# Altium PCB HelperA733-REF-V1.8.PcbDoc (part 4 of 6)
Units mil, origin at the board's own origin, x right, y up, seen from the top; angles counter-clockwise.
Board outline 5905.51 x 4133.86 mil, 2 copper layers (Top, Bottom), stack 12.7 mil thick; 475 components, 355 nets, 1867 pads, 1471 vias.
Unrouted connection lines stored in the file: 1178.
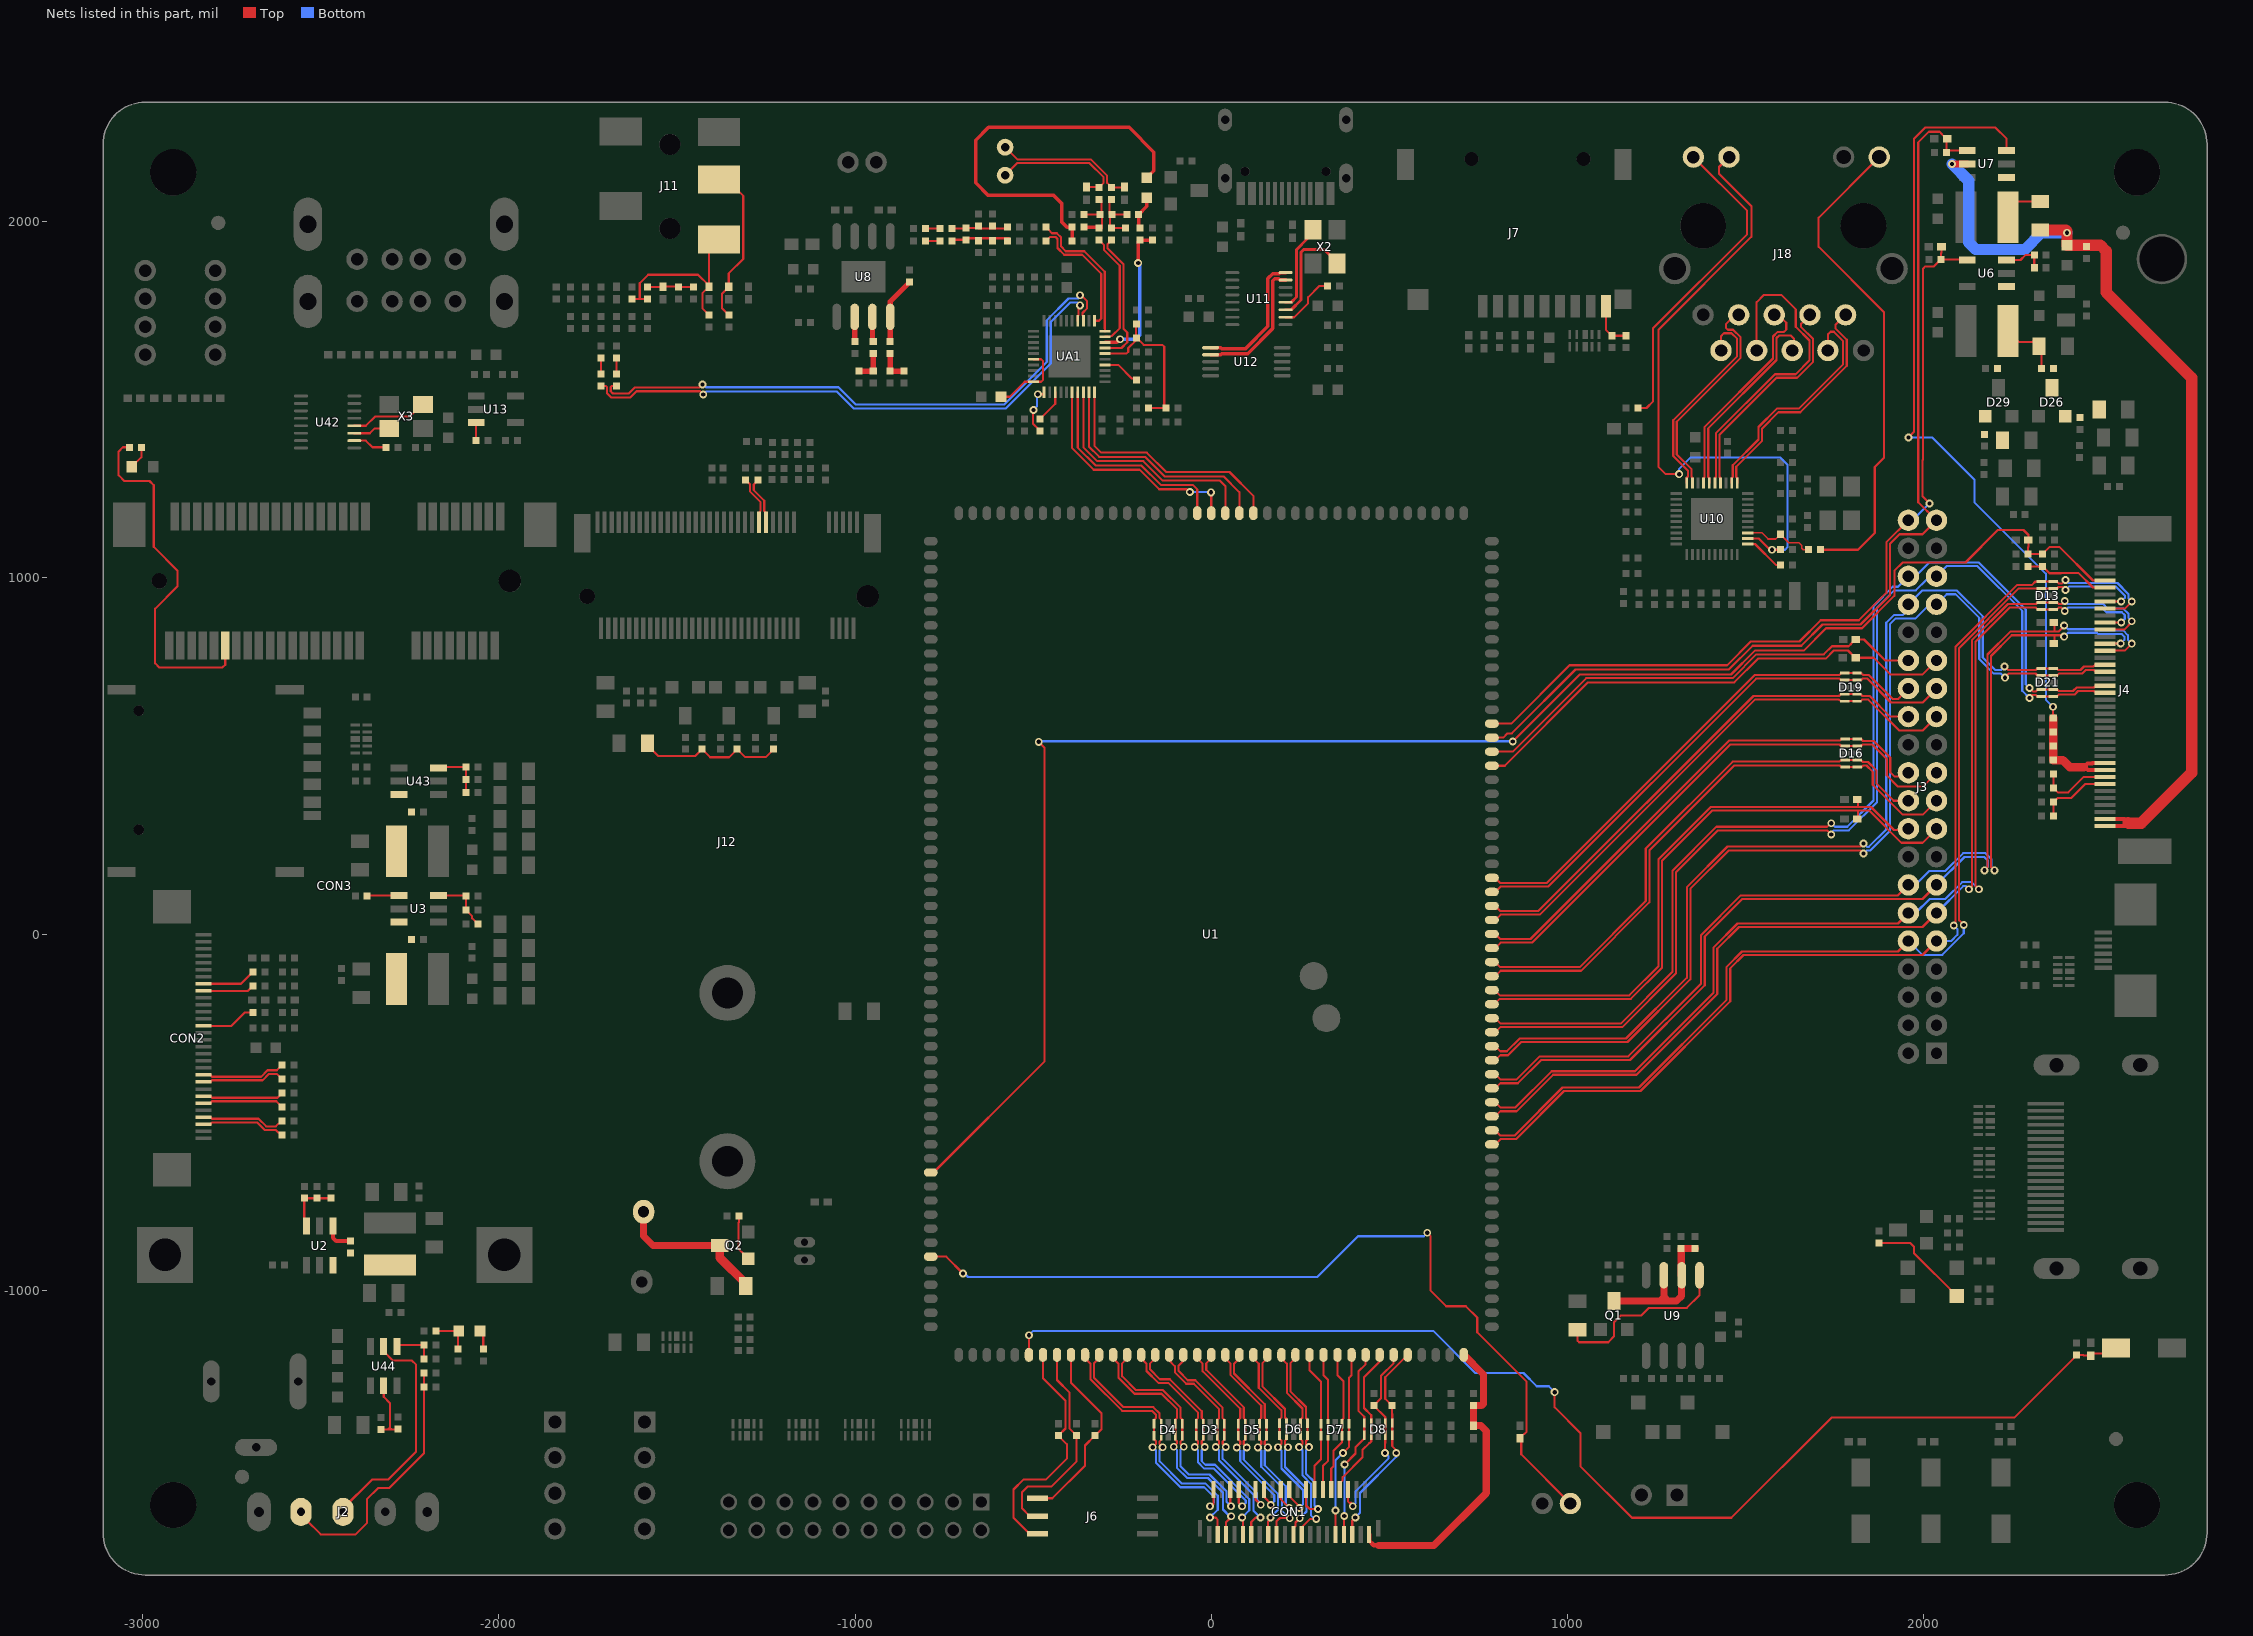
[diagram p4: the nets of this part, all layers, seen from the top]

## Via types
v1: diameter 22, hole 12, Top to Bottom, 1469 vias
v2: diameter 39.37, hole 35.43, Top to Bottom, 2 vias

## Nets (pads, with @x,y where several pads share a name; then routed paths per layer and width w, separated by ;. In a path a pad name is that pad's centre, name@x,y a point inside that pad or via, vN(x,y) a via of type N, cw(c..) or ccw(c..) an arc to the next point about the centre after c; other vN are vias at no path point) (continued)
HUB1-DM3: U11.15 U12.2 | length 378.6
  Top w10: U12.2@-1.97,1625.98 26.65,1625.98 29.5,1628.83 101.91,1628.83 172.8,1699.72 172.8,1833.45 178.42,1839.06 189.74,1839.06 193.17,1835.63 U11.15@208.66,1835.63
HUB1-DP3: U11.16 U12.1 | length 378.9
  Top w10: U12.1@-1.97,1645.67 26.65,1645.67 29.5,1642.83 96.11,1642.83 158.78,1705.49 158.78,1839.68 172.16,1853.06 190.16,1853.06 193.59,1856.5 U11.16@208.66,1856.5
I2S0-BCLK: U1.111 UA1.29 | length 686.7
  Top w6: UA1.29@-343.31,1520.69 -343.31,1368.08 -314.43,1339.2 -186.15,1339.2 -131.51,1284.57 34.33,1284.57 78.74,1240.16 U1.111@78.74,1181.1
I2S0-DIN0: U1.114 UA1.27 | length 606.3
  Top w6: UA1.27@-374.81,1520.69 -374.81,1365.29 -324.72,1315.2 -196.14,1315.2 -141.47,1260.53 -52,1260.53 -39.37,1247.91 U1.114@-39.37,1181.1
I2S0-DOUT0: U1.113 UA1.26 | length 658
  Top w6: UA1.26@-390.56,1520.69 -390.56,1363.83 -329.93,1303.2 -201.11,1303.2 -146.43,1248.52 -68.31,1248.52 v1(-60.24,1240.46) ; v1(-0.82,1239.57) 0,1238.75 U1.113@0,1181.1
  Bottom w6: v1(-60.24,1240.46) -0.34,1240.46 v1(-0.82,1239.57)
I2S0-LRCK: U1.112 UA1.28 | length 674.1
  Top w6: UA1.28@-359.06,1520.69 -359.06,1366.62 -319.64,1327.2 -191.12,1327.2 -136.46,1272.54 24.32,1272.54 39.37,1257.49 U1.112@39.37,1181.1
I2S0-MCLK: U1.110 UA1.30 | length 703.4
  Top w6: UA1.30@-327.56,1520.69 -327.56,1369.53 -309.24,1351.2 -181.17,1351.2 -126.61,1296.64 51.18,1296.64 118.11,1229.71 U1.110@118.11,1181.1
INTB: RE1.2 U10.31 | length 116
  Top w6: U10.31@1505.91,1094.49 1526.19,1094.49 1585.24,1035.43 RE1.2@1597.44,1035.43
IO-RESET: D42.1 K4.1 R54.2 U1.6 | length 3615.7
  Top w6: U1.6@-511.81,-1173.23 U1.6@-511.81,-1181.1 v1(-511.81,-1125.98) ; v1(963.74,-1285.8) 963.74,-1328.12 1036.06,-1400.44 1036.06,-1493.61 1180.9,-1638.46 1459.77,-1638.46 1740.91,-1357.32 2253.9,-1357.32 R54.2@2429.13,-1182.09 2448.11,-1182.09 2449.37,-1183.35 D42.1@2468.5,-1183.35 2468.5,-1181.35 2472.69,-1177.17 2523.62,-1177.17 K4.1@2539.37,-1161.42
  Bottom w6: v1(-511.81,-1125.98) -499.68,-1113.86 622.54,-1113.86 741.03,-1232.34 876.08,-1232.34 913.15,-1269.42 947.35,-1269.42 v1(963.74,-1285.8)
IOVDD-CSI: CON1.39 CP4.1 D12.2 U1.37 | length 874.9
  Top w12: CON1.39@443.04,-1685 443.04,-1702.72 456.18,-1715.86 469.55,-1715.86
  Top w20: 469.55,-1715.86 625.47,-1715.86 771.89,-1569.45 771.89,-1395.3 756.22,-1379.64 D12.2@736.22,-1379.64 CP4.1@736.22,-1323.82 758.78,-1323.82 763.78,-1318.82 763.78,-1236.22 U1.37@708.66,-1181.1
LCD0-EN: D22.1 J3.40 R41.2 U1.81 U6.4 | length 2426.8
  Top w6: U1.81@787.4,590.55 841.66,590.55 1005.44,754.33 1447.71,754.33 1514.54,821.16 1651.14,821.16 1710.62,880.64 1817.44,880.64 1894.67,957.86 1894.67,1099.4 J3.40@1956.69,1161.42 ; v1(2015.75,1208.66) 1996.06,1228.35 1996.06,1329.17 1997.6,1330.71 1997.6,1867.68 2003.94,1874.02 2028.54,1874.02 R41.2@2048.23,1893.7 ; D22.1@2049.5,1929.13 2049.5,1911.97 2048.23,1910.7 R41.2@2048.23,1893.7 ; U6.4@2122.05,1891.73 2131.89,1891.73 2129.92,1893.7 R41.2@2048.23,1893.7
  Bottom w6: J3.40@1956.69,1161.42 1964.57,1169.29 1976.38,1169.29 v1(2015.75,1208.66)
LCD0-HSYNC: D25.1 J3.29 U1.78 | length 1425.7
  Top w6: U1.78@787.4,472.44 823.58,472.44 1057.44,706.3 1468.11,706.3 1534.65,772.83 1724.42,772.83 1747.19,795.6 1787.05,795.6 1807.15,775.5 D25.1@1808.43,775.5 1858.97,775.5 1905.75,728.72 1996.43,728.72 J3.29@2035.43,767.72
LCD0-PWM: D23.1 J3.39 R43.1 U1.80 U7.4 | length 2879.8
  Top w6: U1.80@787.4,551.18 819.39,551.18 831.37,563.16 843.15,563.16 1022.29,742.3 1452.73,742.3 1519.58,809.15 1656.14,809.15 1715.57,868.58 1822.36,868.58 1905.31,951.53 1905.31,1095.89 1931.47,1122.05 1996.06,1122.05 J3.39@2035.43,1161.42 2010.14,1186.71 2009.42,1186.71 1984.25,1211.87 1984.25,2222.02 2014.2,2251.97 2044.29,2251.97 2050.68,2245.57 2050.68,2244.84 2063.24,2232.28 D23.1@2065.24,2232.28 2065.24,2226.66 2063.98,2225.39 R43.1@2063.98,2197.83 ; U7.4@2122.05,2198.82 2064.96,2198.82 R43.1@2063.98,2197.83 ; R43.1@2063.98,2197.83 R43.1@2063.98,2192.91 2059.06,2192.91 R43.1@2063.98,2197.83
LCD0-VSYNC: D24.1 J3.30 U1.79 | length 1324.7
  Top w6: U1.79@787.4,511.81 845.93,511.81 1052.42,718.3 1463.14,718.3 1529.69,784.84 1719.45,784.84 1742.22,807.6 1788.89,807.6 1794.78,813.49 1794.78,814.21 1807.34,826.77 D24.1@1809.34,826.77 1832.2,826.77 1891.25,767.72 J3.30@1956.69,767.72
LCD-PE3: J6.3 R50.2 U1.7 | length 686.3
  Top w6: J6.3@-488.19,-1683.86 -509.84,-1683.86 -555.12,-1638.58 -555.12,-1559.06 -527.56,-1531.5 -464.57,-1531.5 -405.51,-1472.44 -405.51,-1431.69 R50.2@-429.13,-1408.07 -409.13,-1388.07 -409.13,-1310.17 -472.44,-1246.87 U1.7@-472.44,-1181.1
LCD-PE4: J6.2 R49.2 U1.8 | length 609
  Top w6: J6.2@-488.19,-1633.86 -509.84,-1633.86 -531.5,-1612.2 -531.5,-1566.93 -515.75,-1551.18 -448.82,-1551.18 -377.95,-1480.32 R49.2@-377.95,-1408.07 -397.64,-1388.39 -397.64,-1287.4 -433.07,-1251.97 -433.07,-1188.98 U1.8@-433.07,-1181.1
LCD-PE5: J6.1 R48.2 U1.9 | length 537.6
  Top w6: J6.1@-488.19,-1583.86 -446.06,-1583.86 -354.33,-1492.13 -354.33,-1435.63 R48.2@-326.77,-1408.07 -307.93,-1389.23 -307.93,-1345.61 -393.7,-1259.84 U1.9@-393.7,-1181.1
LCD_LR: J4.33 R27.2 R34.1 | length 206
  Top w6: R27.2@2364.17,448.82 R34.1@2364.17,409.45 2376.14,397.49 2385.67,397.49 2385.83,397.64 2405.51,397.64 2448.82,440.94 J4.33@2507.87,440.94
LCD_RST-PL7: C33.2 D28.1 J4.5 R31.2 U1.177 | length 4741
  Top w6: U1.177@-787.4,-669.29 -779.53,-669.29 -468.5,-358.27 -468.5,523.62 v1(-484.25,539.37) ; v1(846.19,540.39) 1034.14,728.35 1458.66,728.35 1525.59,795.28 1662.49,795.28 1725.48,858.27 1826.19,858.27 1917.32,949.4 1917.32,1019.72 1940.54,1042.94 2116.74,1042.94 2207.66,1133.86 2279.53,1133.86 2293.59,1119.8 D28.1@2293.59,1106.3 2293.59,1087.17 2292.32,1085.9 C33.2@2292.32,1066.93 R31.2@2333.66,1066.93 2353.35,1086.61 2380.36,1086.61 2474.84,992.13 J4.5@2507.87,992.13
  Bottom w6: v1(-484.25,539.37) -484.25,540.95 846.19,540.95 v1(846.19,540.39)
LCD_UD: J4.34 R28.2 R35.1 | length 204.3
  Top w6: R28.2@2364.17,330.71 R35.1@2364.17,370.08 2375.98,381.89 2413.39,381.89 2452.76,421.26 J4.34@2507.87,421.26
LDOIN/RSTN: CA15.1 RA17.1 RA18.2 RA19.1 UA1.36 | length 475.1
  Top w6: UA1.36@-298.04,1628.96 -238.44,1628.96 -233.1,1634.29 -233.1,1644.76 -209.65,1668.22 CA15.1@-209.65,1673.23 ; RA18.2@-209.65,1712.6 -211.59,1710.66 -211.59,1674.83 -211.59,1673.23 CA15.1@-209.65,1673.23 ; RA17.1@-176.18,1476.38 RA19.1@-126.97,1476.38 ; RA19.1@-120.88,1476.38 RA19.1@-126.97,1476.38 ; CA15.1@-209.65,1673.23 -189.96,1653.54 -137.41,1653.54 -132.02,1648.15 -132.02,1481.43 RA19.1@-126.97,1476.38
LED0_AD0: J18.13 R84.2 U10.32 | length 1815.5
  Top w6: v1(1313.18,1290.73) 1275.4,1290.73 1255.63,1310.5 1255.63,1696.57 1515.75,1956.69 1515.75,2043.31 1425.2,2133.86 1425.2,2152.76 J18.13@1453.15,2180.71 ; U10.32@1505.91,1110.24 1536.8,1110.24 1568.29,1078.74 v1(1573.88,1078.74) R84.2@1597.44,1078.74
  Bottom w6: v1(1313.18,1290.73) 1313.18,1305.68 1344.61,1337.11 1597.63,1337.11 1617.01,1317.73 1617.01,1085.21 1610.54,1078.74 v1(1573.88,1078.74)
LED1_AD1: R82.2 R83.2 U10.33 | length 205.4
  Top w5: U10.33@1505.91,1125.98 1545.75,1125.98 1562.91,1108.83 1584.22,1108.83 R83.2@1597.44,1122.05 1621.06,1098.43 1649.61,1098.43 1657.48,1090.55 1657.48,1082.68 1661.42,1078.74 R82.2@1676.18,1078.74
LED+: C42.1 C43.1 D32.2 J4.39 J4.40 U7.5 | length 2783.8
  Top w6: v1@2398.27,1975.75 2402.83,1980.31 v1(2401.57,1968.5)
  Top w11.81: J4.40@2507.87,303.15 2562.99,303.15 2572.77,312.93 2562.87,322.83 J4.39@2507.87,322.83
  Top w19.68: v1(2078.74,2161.42) U7.5@2122.05,2161.42
  Top w31.5: D32.2@2326.77,1975.75 2394.33,1975.75 v1(2401.57,1968.5) ; v1@2398.27,1975.75 2401.57,1972.44 v1(2401.57,1968.5) ; 2572.77,312.93 2574.68,311.02 2610.24,311.02 2751.97,452.76 2751.97,1561.05 2511.81,1801.21 2511.81,1916.96 2495.3,1933.46 C42.1@2401.57,1933.46 v1(2401.57,1968.5)
  Bottom w31.5: v1(2078.74,2161.42) 2125.98,2114.17 2125.98,1940.94 2145.67,1921.26 2283.46,1921.26 2330.71,1968.5 v1(2401.57,1968.5)
LED-: J4.31 J4.32 R44.1 R45.1 R46.1 R47.1 U7.3 | length 2498.2
  Top w6: v1(1956.69,1393.7) 1972.44,1409.45 1972.44,2232.28 2003.94,2263.78 2200.79,2263.78 2232.28,2232.28 U7.3@2232.28,2198.82 ; v1(2362.2,637.8) 2362.2,606.3 R44.1@2363.19,606.3
  Top w11.81: J4.32@2507.87,460.63 2460.63,460.63 2452.76,468.5 2448.82,468.5 2459.02,478.71 2472.05,478.71 2473.66,480.31 J4.31@2507.87,480.32
  Top w23.62: R44.1@2363.19,606.3 R46.1@2363.19,566.93 R47.1@2363.19,527.56 R45.1@2363.19,488.19 2389.76,488.19 2409.45,468.5 2448.82,468.5
  Bottom w6: v1(1956.69,1393.7) 2023.62,1393.7 2141.67,1275.65 2141.67,1211.94 2342.52,1011.09 2342.52,657.48 v1(2362.2,637.8)
LRADC0: D43.2 J9.1 U1.183 | length 2444.6
  Top w6: U1.183@-787.4,-905.51 -744.09,-905.51 v1(-696.85,-952.76) ; v1(606.3,-838.58) 615.67,-847.95 615.67,-1000.96 659.38,-1044.67 714.67,-1044.67 746.56,-1076.56 746.56,-1118.1 885.14,-1256.68 885.14,-1396.64 879.15,-1402.63 866.14,-1411.31 D43.2@866.14,-1415.64 866.14,-1417.64 870.08,-1421.57 870.08,-1460.63 J9.1@1007.87,-1598.43
  Bottom w6: v1(-696.85,-952.76) -692.91,-952.76 -683.03,-962.64 297.44,-962.64 411.57,-848.5 596.38,-848.5 v1(606.3,-838.58)
LVDS0-CKN: D21.1 D21.10 J3.34 J4.17 U1.58 | length 2945
  Top w6: U1.58@787.4,-314.96 797.24,-314.96 811.43,-329.15 829.6,-329.15 865.49,-293.26 1164.2,-293.26 1334.79,-122.67 1334.79,131.39 1449.02,245.62 1822.39,245.62 v1(1830.89,254.12) ; v1(2226.54,751.08) 2236.58,741.04 2314.47,741.04 2318.81,745.39 D21.10@2363.5,745.39 2373.36,745.39 2377.7,741.04 2439.69,741.04 2449.44,750.79 2475.85,750.79 2480.97,755.91 J4.17@2507.87,755.91
  Bottom w6: v1(1830.89,254.12) 1840.38,244.63 1845.75,244.63 1894.59,293.47 1894.59,873.75 1916.67,895.83 1941.31,895.83 1956.69,911.21 J3.34@1956.69,925.2 1995.69,964.2 2092.65,964.2 2165.3,891.54 2165.3,776.17 2200.5,740.97 2216.43,740.97 v1(2226.54,751.08)
LVDS0-CKP: D21.2 D21.9 J3.33 J4.18 U1.57 | length 2938.3
  Top w6: U1.57@787.4,-354.33 797.24,-354.33 811.43,-340.15 832.77,-340.15 869.64,-303.28 1168.39,-303.28 1344.8,-126.87 1344.8,126.82 1452.6,234.62 1822.39,234.62 v1(1830.89,226.12) ; v1(2227.76,719.64) 2229.37,719.75 2229.25,721.54 2238.75,731.04 2313.44,731.04 2318.78,725.7 D21.9@2363.5,725.7 2373.78,725.7 2379.01,730.93 2443.9,730.93 2453.53,740.56 2477.14,740.56 2481.48,736.22 J4.18@2507.87,736.22
  Bottom w6: v1(1830.89,226.12) 1839.39,234.62 1849.91,234.62 1904.62,289.33 1904.62,869.63 1920.81,885.83 1976.99,885.83 2016.36,925.2 J3.33@2035.43,925.2 2063.84,953.6 2089.1,953.6 2155.3,887.4 2155.3,772.03 2196.36,730.97 2216.43,730.97 v1(2227.76,719.64)
LVDS0-D0N: D13.2 D13.9 J3.10 J4.8 U1.52 | length 3081.1
  Top w6: U1.52@787.4,-551.18 797.24,-551.18 811.43,-565.37 851.3,-565.37 985.85,-430.82 1200.47,-430.82 1446.38,-184.91 1446.38,-92.35 1489.68,-49.06 1927.32,-49.06 J3.10@1956.69,-19.69 ; v1(2112.12,25.52) 2098.97,38.66 2098.97,84.14 2099.14,97.64 2099.14,802.98 2266.17,970.02 2329.42,970.02 D13.2@2329.42,969.79 D13.9@2363.5,969.79 2373.61,969.79 2377.95,974.14 2389.11,974.14 v1(2397.61,965.64) ; J4.8@2507.87,933.07 2554.31,933.07 2554.31,933.42 v1(2553.74,933.42)
  Bottom w6: J3.10@1956.69,-19.69 1995.69,-58.68 2051.59,-58.68 2112.12,1.84 v1(2112.12,25.52) ; v1(2397.61,965.64) 2407.08,975.11 2539.28,975.11 2564.17,950.22 2564.17,943.85 v1(2553.74,933.42)
LVDS0-D0P: D13.1 D13.10 J3.9 J4.9 U1.51 | length 3112.1
  Top w6: U1.51@787.4,-590.55 797.24,-590.55 812.36,-575.43 855.48,-575.43 990.08,-440.83 1204.64,-440.83 1456.42,-189.05 1456.42,-96.46 1493.82,-59.06 1996.06,-59.06 J3.9@2035.43,-19.69 ; v1(2084.08,23.97) 2088.97,28.86 2088.97,88.28 2089.14,101.78 2089.14,807.12 2262.03,980.02 2303.86,980.02 2313.33,989.48 D13.10@2363.5,989.48 2373.26,989.48 2378.6,984.14 2388.11,984.14 v1(2397.61,993.64) ; J4.9@2507.87,913.39 2563.98,913.39 v1(2583.66,933.07)
  Bottom w6: J3.9@2035.43,-19.69 2076.45,-19.69 2094.03,-2.1 2094.03,14.01 v1(2084.08,23.97) ; v1(2397.61,993.64) 2406.11,985.14 2543.4,985.14 2574.18,954.37 2574.18,942.56 v1(2583.66,933.07)
LVDS0-D1N: D13.5 D13.6 J3.12 J4.11 U1.54 | length 2967.4
  Top w6: U1.54@787.4,-472.44 797.24,-472.44 811.43,-486.63 853.85,-486.63 955.39,-385.08 1189.18,-385.08 1410.01,-164.25 1410.01,-37.4 1477.09,29.68 1927.32,29.68 J3.12@1956.69,59.06 ; v1(2154.38,125.54) 2144.88,135.04 2144.88,820.44 2240.5,916.06 2314.14,916.06 2319.46,910.74 D13.6@2363.5,910.74 2373.44,910.74 2378.77,916.07 2385.87,916.07 v1(2395.37,906.58) ; J4.11@2507.87,874.02 2554.12,874.02 v1(2554.12,874.38)
  Bottom w6: J3.12@1956.69,59.06 1976.75,59.06 2016.12,98.43 2060.54,98.43 2107.66,145.54 2134.66,145.54 2154.52,125.68 v1(2154.38,125.54) ; v1(2395.37,906.58) 2404.85,916.06 2499.6,916.06 2512.39,903.27 2555.88,903.27 2563.85,895.3 2563.85,884.1 v1(2554.12,874.38)
LVDS0-D1P: D13.4 D13.7 J3.11 J4.12 U1.53 | length 3002.4
  Top w6: U1.53@787.4,-511.81 797.24,-511.81 811.43,-497.63 857.06,-497.63 959.57,-395.12 1193.31,-395.12 1420.07,-168.36 1420.07,-41.48 1481.24,19.68 1996.06,19.68 J3.11@2035.43,59.06 ; v1(2126.38,125.54) 2134.88,134.04 2134.88,824.58 2236.38,926.08 2314.7,926.08 2319.04,930.42 D13.7@2363.5,930.42 2374.05,930.42 2378.39,926.08 2386.87,926.08 v1(2395.37,934.58) ; J4.12@2507.87,854.33 2562.36,854.33 2583.66,875.63 v1(2583.66,877.95)
  Bottom w6: J3.11@2035.43,59.06 2110.71,134.33 2117.59,134.33 v1(2126.38,125.54) ; v1(2395.37,934.58) 2403.87,926.08 2503.78,926.08 2516.44,913.42 2559.99,913.42 2573.99,899.42 2573.99,887.63 v1(2583.66,877.95)
LVDS0-D2N: D81.1 J3.14 J4.14 U1.56 | length 2907.6
  Top w6: U1.56@787.4,-393.7 797.24,-393.7 811.43,-407.89 857.13,-407.89 921.62,-343.39 1170.29,-343.39 1374.98,-138.7 1374.98,-2.73 1486.13,108.42 1927.32,108.42 J3.14@1956.69,137.8 ; v1(2198.13,178.59) 2188.63,188.09 2188.63,780.46 2246.76,838.58 2365.93,838.58 ; D81.1@2364.97,814.93 2367.13,814.93 2367.13,837.62 2365.93,838.58 ; v1(2393.7,834.65) 2389.76,838.58 2365.93,838.58 ; J4.14@2507.87,814.96 2555.26,814.96 v1(2552.42,815.52)
  Bottom w6: J3.14@1956.69,137.8 1976.38,137.8 2015.38,176.8 2060.29,176.8 2110.48,226.99 2173.13,226.99 2189.63,210.49 2189.63,187.09 v1(2198.13,178.59) ; v1(2393.7,834.65) 2404.45,845.39 2485.77,845.39 2489.03,842.13 2555.28,842.13 2562.76,834.65 2562.76,825.86 v1(2552.42,815.52)
LVDS0-D2P: D80.1 J3.13 J4.15 U1.55 | length 2960.8
  Top w6: U1.55@787.4,-433.07 797.24,-433.07 811.43,-418.89 860.27,-418.89 925.75,-353.41 1175.28,-353.41 1385.03,-143.66 1385.03,-6.82 1490.27,98.43 1996.06,98.43 J3.13@2035.43,137.8 ; v1(2170.13,178.59) 2178.63,187.09 2178.63,784.61 2242.76,848.74 2366.66,848.74 ; D80.1@2366.66,870.5 2366.66,848.74 ; v1(2393.7,866.14) 2393.7,864.72 2377.72,848.74 2366.66,848.74 ; J4.15@2507.87,795.28 2563.98,795.28 v1(2583.66,814.96)
  Bottom w6: J3.13@2035.43,137.8 2113.95,216.31 2169.66,216.31 2179.54,206.43 2179.54,188 v1(2170.13,178.59) ; v1(2393.7,866.14) 2404.45,855.39 2489.91,855.39 2493.18,852.13 2559.42,852.13 2572.76,838.79 2572.76,825.86 v1(2583.66,814.96)
LVDS0-D3N: D21.4 D21.7 J3.36 J4.20 U1.60 | length 3045.4
  Top w6: U1.60@787.4,-236.22 797.24,-236.22 812.42,-251.4 1149.3,-251.4 1294.3,-106.4 1294.3,177.76 1417.58,301.05 1728.51,301.05 1738.49,311.02 v1(1740.16,311.02) ; v1(2296.47,690.49) 2305.92,681.03 2314.69,681.03 2319.99,686.33 D21.7@2363.5,686.33 2374.49,686.33 2378.83,681.99 2418.66,681.99 2428.73,692.06 2477.68,692.06 2482.47,696.85 J4.20@2507.87,696.85
  Bottom w6: v1(1740.16,311.02) 1744.09,311.02 1741.63,309.55 1750.13,301.05 1785.17,301.05 1858.84,374.72 1858.84,920.83 1912.65,974.64 1927.4,974.64 J3.36@1956.69,1003.94 1976.61,1003.94 2015.61,1042.94 2154.25,1042.94 2286.18,911 2286.18,700.77 v1(2296.47,690.49)
LVDS0-D3P: D21.5 D21.6 J3.35 J4.21 U1.59 | length 3060.1
  Top w6: U1.59@787.4,-275.59 797.24,-275.59 811.43,-261.4 1153.45,-261.4 1304.31,-110.55 1304.31,173.59 1420.76,290.05 1729.64,290.05 v1(1740.16,279.53) ; v1(2296.47,662.49) 2304.97,670.99 2313.71,670.99 2318.05,666.65 D21.6@2363.5,666.65 2373.28,666.65 2378.56,671.93 2422.79,671.93 2432.87,682.01 2477.23,682.01 2482.08,677.17 J4.21@2507.87,677.17
  Bottom w6: v1(1740.16,279.53) 1738.24,281.55 1747.57,290.88 1789.19,290.88 1868.94,370.63 1868.94,916.79 1916.72,964.57 1977.2,964.57 2007.41,994.78 2026.27,994.78 J3.35@2035.43,1003.94 2064.43,1032.94 2150.1,1032.94 2276.18,906.86 2276.18,682.49 2296.32,662.35 v1(2296.47,662.49)
LVDS1-CKN: D19.2 D19.9 J3.26 U1.68 | length 1453.4
  Top w6: U1.68@787.4,78.74 797.24,78.74 811.43,64.55 918.04,64.55 1521.64,668.15 1761.67,668.15 1766.75,673.23 D19.2@1812.32,673.23 1822.68,673.23 1828.01,667.9 1847.97,667.9 1905.63,610.24 J3.26@1956.69,610.24
LVDS1-CKP: D19.1 D19.10 J3.25 U1.67 | length 1559.9
  Top w6: U1.67@787.4,39.37 797.24,39.37 812.41,54.54 922.22,54.54 1525.57,657.89 1761.97,657.89 1766.31,653.54 D19.1@1812.32,653.54 1822.43,653.54 1826.77,657.89 1843.84,657.89 1930.49,571.24 1996.43,571.24 J3.25@2035.43,610.24
LVDS1-D0N: D83.1 J3.18 U1.62 | length 1628.5
  Top w6: U1.62@787.4,-157.48 795.28,-157.48 809.96,-172.17 1173.08,-172.17 1255.14,-90.11 1255.14,209.61 1401.92,356.39 1404.96,356.39 1405.03,356.46 1814.96,356.46 ; D83.1@1813.28,377.95 1814.96,377.95 1814.96,356.46 ; J3.18@1956.69,295.28 1960.25,291.72 1916.39,291.72 1851.65,356.46 1814.96,356.46
LVDS1-D0P: D82.1 J3.17 U1.61 | length 1727.5
  Top w6: U1.61@787.4,-196.85 795.28,-196.85 809.96,-182.17 1177.22,-182.17 1265.14,-94.25 1265.14,205.47 1406.13,346.46 1814.96,346.46 ; D82.1@1813.28,322.83 1814.96,322.83 1814.96,346.46 ; J3.17@2035.43,295.28 1996.43,256.28 1936.82,256.28 1846.64,346.46 1814.96,346.46
LVDS1-D1N: D16.2 D16.9 J3.20 U1.64 | length 1571.5
  Top w6: U1.64@787.4,-78.74 797.24,-78.74 811.43,-92.93 1033.82,-92.93 1219.6,92.86 1219.6,239.84 1463.61,483.85 1762.98,483.85 1767.32,488.19 D16.9@1779.22,488.19 D16.2@1813.3,488.19 1813.3,488.91 1823.17,488.91 1829.22,482.85 1843.07,482.85 ; 1843.08,482.86 1866.71,459.23 1866.71,422.99 1915.68,374.02 J3.20@1956.69,374.02
LVDS1-D1P: D16.1 D16.10 J3.19 U1.63 | length 1676.1
  Top w6: U1.63@787.4,-118.11 797.24,-118.11 812.41,-102.94 1037.95,-102.94 1229.7,88.81 1229.7,234.33 1468.22,472.85 1764,472.85 1768.34,468.5 D16.10@1779.22,468.5 D16.1@1813.3,468.5 1825.96,468.5 1830.3,472.85 1838.95,472.85 1856.71,455.09 1856.71,418.85 1940.54,335.02 1996.43,335.02 J3.19@2035.43,374.02
LVDS1-D2N: D16.5 D16.6 J3.22 U1.66 | length 1486.6
  Top w6: U1.66@787.4,0 797.24,0 811.43,-14.19 895.92,-14.19 1453.01,542.9 1763.64,542.9 1767.98,547.24 D16.6@1779.22,547.24 D16.5@1813.3,547.24 1823.86,547.24 1829.15,541.95 1859.08,541.95 1905.69,495.34 1905.69,454.2 1918.16,441.72 1956.69,441.72 J3.22@1956.69,452.76
LVDS1-D2P: D16.4 D16.7 J3.21 U1.65 | length 1580
  Top w6: U1.65@787.4,-39.37 797.24,-39.37 812.39,-24.22 900.08,-24.22 1456.2,531.9 1763.08,531.9 1767.42,527.56 D16.7@1779.22,527.56 D16.4@1813.3,527.56 1823.72,527.56 1828.06,531.9 1854.99,531.9 1895.69,491.2 1895.69,445.69 1927.63,413.76 1996.43,413.76 J3.21@2035.43,452.76
LVDS1-D3N: D19.5 D19.6 J3.28 U1.70 | length 1461.3
  Top w6: U1.70@787.4,157.48 797.24,157.48 811.43,143.29 941.92,143.29 1525.59,726.96 1762.55,726.96 1767.88,732.28 1824.23,732.28 1829.55,726.96 1845,726.96 1911.98,659.98 1928.05,659.98 1933.36,665.28 1933.36,665.64 J3.28@1956.69,688.98
LVDS1-D3P: D19.4 D19.7 J3.27 U1.69 | length 1543.6
  Top w6: U1.69@787.4,118.11 797.24,118.11 812.42,133.29 946.08,133.29 1529.73,716.94 1762.36,716.94 1766.7,712.6 1824.61,712.6 1828.96,716.96 1840.85,716.96 1907.84,649.98 1996.43,649.98 J3.27@2035.43,688.98
MBIAS: CA4.2 RA1.2 UA1.38 | length 412.4
  Top w9.84: UA1.38@-298.04,1660.46 -264.74,1660.46 v1(-255.91,1669.29) ; v1(-205.27,1883.47) -205.27,1943.35 RA1.2@-200.79,1947.83 CA4.2@-165.35,1947.83
  Bottom w9.84: v1(-255.91,1669.29) -211.51,1669.29 -200.72,1680.09 -200.72,1878.92 v1(-205.27,1883.47)
MCSI0-MCLK: CON1.26 D7.1 D7.10 U1.26 | length 399.1
  Top w6: U1.26@275.59,-1181.1 275.59,-1224.41 308.1,-1256.91 D7.1@308.1,-1408.34 308.1,-1473.84 289.5,-1492.44 CON1.26@289.5,-1559.02
MCSI2-MCLK: CON1.28 D7.2 D7.9 U1.27 | length 389.3
  Top w6: CON1.28@313.12,-1559.02 313.12,-1493.12 327.79,-1478.46 D7.2@327.79,-1408.34 327.79,-1251.63 314.96,-1238.81 U1.27@314.96,-1181.1
MCSI-RST-F: CON1.31 D7.5 D7.6 U1.29 | length 522.7
  Top w6: v1(348.44,-1618) 348.55,-1618.11 CON1.31@348.55,-1685 ; v1(369.45,-1456.47) 386.84,-1439.09 D7.5@386.84,-1408.34 386.84,-1245.04 393.7,-1238.18 U1.29@393.7,-1181.1
  Bottom w6: v1(348.44,-1618) 348.44,-1477.48 v1(369.45,-1456.47)
MCSI-RST-R: CON1.32 D8.4 D8.7 U1.31 | length 441.6
  Top w6: CON1.32@360.36,-1559.02 360.36,-1541.3 368.73,-1532.93 368.73,-1524.49 424.57,-1468.66 424.57,-1447.87 443.53,-1428.91 444.25,-1428.91 448.81,-1424.35 D8.7@448.81,-1406.8 D8.4@448.81,-1372.72 448.81,-1350.8 428.5,-1330.49 428.5,-1243.87 472.44,-1199.94 U1.31@472.44,-1181.1
MCSI-SCK-TWI2: CON1.34 D8.2 D8.9 R15.2 U1.32 | length 572.9
  Top w6: CON1.34@383.98,-1559.02 383.98,-1593.12 388.33,-1597.47 391.67,-1596.42 v1(397.01,-1606.08) v1@390.2,-1597.89 ; v1(487.56,-1456.47) 487.56,-1429.54 488.18,-1428.91 D8.9@488.18,-1406.8 D8.2@488.18,-1372.72 488.18,-1355.72 R15.2@456.06,-1323.6 476.38,-1303.28 476.38,-1240.16 511.81,-1204.72 U1.32@511.81,-1181.1
  Bottom w6: v1(397.01,-1606.08) 404.99,-1598.1 404.99,-1564.11 497.63,-1471.47 497.63,-1466.54 v1(487.56,-1456.47)
MCSI-SDA-TWI2: CON1.35 D8.1 D8.10 R16.2 U1.33 | length 593.8
  Top w6: CON1.35@395.79,-1685 395.79,-1646.1 v1(404.41,-1637.48) ; v1(519.06,-1456.47) 519.06,-1448.6 507.87,-1437.42 D8.10@507.87,-1406.8 D8.1@507.87,-1372.72 507.87,-1346.85 507.24,-1346.22 R16.2@507.24,-1323.6 488.27,-1304.63 488.27,-1244.01 U1.33@551.18,-1181.1
  Bottom w6: v1(404.41,-1637.48) 417.2,-1624.69 417.2,-1568.9 519.06,-1467.05 v1(519.06,-1456.47)
MCSI-STBY-F: CON1.30 D7.4 D7.7 U1.28 | length 398.9
  Top w6: CON1.30@336.74,-1559.02 336.74,-1500.01 343.43,-1493.33 343.43,-1449.7 367.16,-1425.97 D7.4@367.16,-1408.34 367.16,-1363.23 370.9,-1359.49 370.9,-1255.39 354.33,-1238.82 U1.28@354.33,-1181.1
MCSI-STBY-R: CON1.33 D8.5 D8.6 U1.30 | length 543.6
  Top w6: CON1.33@372.17,-1685 372.17,-1634.85 v1(373.39,-1633.64) ; v1(374.23,-1488.88) 404.88,-1458.23 404.88,-1440.21 429.13,-1415.96 D8.6@429.13,-1406.8 D8.5@429.13,-1372.72 429.13,-1354.82 412.76,-1338.44 412.76,-1228.13 433.07,-1207.81 U1.30@433.07,-1181.1
  Bottom w6: v1(373.39,-1633.64) 373.39,-1491.91 372.3,-1490.81 v1(374.23,-1488.88)
MCSIA-CKN: CON1.14 D5.1 D5.10 U1.18 | length 583.2
  Top w6: U1.18@-39.37,-1181.1 -39.37,-1190.94 -24.21,-1206.1 -24.21,-1227.26 81.12,-1332.59 81.12,-1358.36 75.81,-1363.67 D5.1@75.81,-1408.34 75.81,-1419.03 81.08,-1424.3 81.08,-1431.68 v1(71.66,-1441.1) ; CON1.14@147.76,-1559.02 147.76,-1579.74 168.62,-1600.6 170.22,-1602.2 v1(166.77,-1602.45)
  Bottom w6: v1(71.66,-1441.1) 81.1,-1450.55 81.1,-1479.47 176.82,-1575.19 176.82,-1592.4 v1(166.77,-1602.45)
MCSIA-CKP: CON1.15 D5.2 D5.9 U1.19 | length 619.4
  Top w6: U1.19@0,-1181.1 0,-1190.94 -14.19,-1205.13 -14.19,-1223.14 91.16,-1328.48 91.16,-1358.58 95.5,-1362.93 D5.2@95.5,-1408.34 95.5,-1418.97 91.16,-1423.32 91.16,-1432.6 v1(99.66,-1441.1) ; CON1.15@159.57,-1685 159.57,-1648.9 168.39,-1640.08 169.73,-1638.74 v1(165.96,-1637.65)
  Bottom w6: v1(99.66,-1441.1) 91.16,-1449.6 91.16,-1475.22 186.84,-1570.9 186.84,-1616.76 v1(165.96,-1637.65)
MCSIA-D0N: CON1.11 D3.4 D3.7 U1.16 | length 652.5
  Top w6: U1.16@-118.11,-1181.1 -118.13,-1197.07 -102.26,-1212.94 -102.26,-1230.38 -70.27,-1262.37 -49.2,-1262.37 21.92,-1333.49 21.92,-1358.36 16.76,-1363.52 D3.4@16.76,-1408.34 16.76,-1418.65 22.08,-1423.97 22.08,-1430.58 v1(12.6,-1440.06) ; CON1.11@112.33,-1685 112.33,-1650.53 125.06,-1637.8 137.18,-1637.8 137.18,-1637.72 v1(137.87,-1637.72)
  Bottom w6: v1(12.6,-1440.06) 21.74,-1449.2 21.74,-1476.84 118.67,-1573.77 118.67,-1618.52 v1(137.87,-1637.72)
MCSIA-D0P: CON1.12 D3.5 D3.6 U1.17 | length 596
  Top w6: U1.17@-78.74,-1181.1 -79.35,-1181.71 -79.35,-1198.88 -92.25,-1211.78 -92.25,-1226.23 -66.13,-1252.35 -45.06,-1252.35 31.93,-1329.34 31.93,-1358.9 36.44,-1363.41 D3.5@36.44,-1408.34 36.44,-1419.86 32.1,-1424.2 32.1,-1431.56 v1(40.6,-1440.06) ; CON1.12@124.14,-1559.02 124.14,-1587.38 138.7,-1601.94 v1(138.7,-1602.04)
  Bottom w6: v1(40.6,-1440.06) 31.77,-1448.89 31.77,-1472.68 128.69,-1569.6 128.69,-1588.41 140.51,-1600.23 v1(138.7,-1602.04)
MCSIA-D1N: CON1.8 D3.1 D3.10 U1.14 | length 646.3
  Top w6: U1.14@-196.85,-1181.1 -196.85,-1190.94 -181.68,-1206.12 -181.68,-1226.55 -148.43,-1259.8 -120.92,-1259.8 -36.98,-1343.74 -36.98,-1358.21 -42.3,-1363.53 D3.1@-42.3,-1408.34 -42.3,-1419.09 -37.05,-1424.34 -37.05,-1430.3 v1(-46.45,-1439.7) ; CON1.8@76.9,-1559.02 76.9,-1596.58 v1(86.61,-1606.3)
  Bottom w6: v1(-46.45,-1439.7) -37.07,-1449.08 -37.07,-1483.5 -20.78,-1499.79 6.17,-1499.79 96.58,-1590.2 96.58,-1596.33 v1(86.61,-1606.3)
MCSIA-D1P: CON1.9 D3.2 D3.9 U1.15 | length 676.7
  Top w6: U1.15@-157.48,-1181.1 -157.48,-1190.94 -171.67,-1205.13 -171.67,-1222.35 -144.23,-1249.78 -116.79,-1249.78 -26.95,-1339.62 -26.95,-1358.36 -22.61,-1362.7 D3.2@-22.61,-1408.34 -22.61,-1419.52 -26.95,-1423.87 -26.95,-1431.2 v1(-18.45,-1439.7) ; v1(86.61,-1637.8) 88.71,-1639.89 CON1.9@88.71,-1685
  Bottom w6: v1(-18.45,-1439.7) -26.95,-1448.2 -26.95,-1479.42 -16.58,-1489.79 10.34,-1489.79 106.61,-1586.07 106.61,-1617.8 v1(86.61,-1637.8)
MCSIA-D2N: CON1.5 D4.4 D4.7 U1.12 | length 741.9
  Top w6: U1.12@-275.59,-1181.1 -275.59,-1190.94 -260.43,-1206.11 -260.43,-1245.39 -215.51,-1290.31 -139.95,-1290.31 -96.03,-1334.23 -96.03,-1357.46 -101.35,-1362.77 -101.35,-1419.21 -96.07,-1424.49 -96.07,-1429.66 v1(-105.51,-1439.1) ; CON1.5@41.46,-1685 41.46,-1651.45 55.12,-1637.8 55.65,-1634.81 v1(55.67,-1634.35)
  Bottom w6: v1(-105.51,-1439.1) -96.67,-1447.94 -96.67,-1497.63 -67.43,-1526.87 -9.04,-1526.87 32.68,-1568.59 32.68,-1615.36 53.67,-1636.35 53.89,-1636.57 55.65,-1634.81 v1(55.67,-1634.35)
MCSIA-D2P: CON1.6 D4.5 D4.6 U1.13 | length 695.4
  Top w6: U1.13@-236.22,-1181.1 -236.22,-1190.94 -250.41,-1205.13 -250.41,-1241.23 -211.32,-1280.31 -135.5,-1280.31 -86.01,-1329.8 -86.01,-1358.35 -81.67,-1362.69 -81.67,-1419.64 -86.01,-1423.98 -86.01,-1430.6 v1(-77.51,-1439.1) ; CON1.6@53.28,-1559.02 53.28,-1604.46 v1(55.12,-1606.3)
  Bottom w6: v1(-77.51,-1439.1) -86.67,-1448.26 -86.67,-1493.34 -63.14,-1516.87 -4.85,-1516.87 42.68,-1564.4 42.68,-1593.87 v1(55.12,-1606.3)
MCSIA-D3N: CON1.2 D4.1 D4.10 U1.10 | length 733.3
  Top w6: U1.10@-354.33,-1181.1 -354.33,-1190.94 -339.27,-1206.01 -339.27,-1249.46 -250.42,-1338.31 -166.63,-1338.31 -155.23,-1349.71 -155.23,-1357.89 -160.41,-1363.07 D4.1@-160.41,-1408.34 -160.41,-1418.69 -155.1,-1424 -155.1,-1430.94 v1(-164.56,-1440.4) ; v1(-3.94,-1606.3) 6.03,-1600.52 CON1.2@6.03,-1559.02
  Bottom w6: v1(-164.56,-1440.4) -155.13,-1449.83 -155.13,-1484.26 -86.56,-1552.83 -20.01,-1552.83 7.87,-1580.71 7.87,-1594.49 v1(-3.94,-1606.3)
MCSIA-D3P: CON1.3 D4.2 D4.9 U1.11 | length 779.5
  Top w6: U1.11@-314.96,-1181.1 -314.96,-1190.94 -329.15,-1205.13 -329.15,-1245.19 -246.24,-1328.09 -162.66,-1328.09 -145.06,-1345.69 -145.06,-1358.96 -140.72,-1363.31 D4.2@-140.72,-1408.34 -140.72,-1419.68 -145.06,-1424.03 -145.06,-1431.9 v1(-136.56,-1440.4) ; v1(-3.94,-1637.8) 11.81,-1637.8 17.84,-1643.82 CON1.3@17.84,-1685
  Bottom w6: v1(-136.56,-1440.4) -145.06,-1448.9 -145.06,-1480.12 -82.38,-1542.81 -15.81,-1542.81 18.03,-1576.65 18.03,-1615.83 v1(-3.94,-1637.8)
MCSIC-CKN: CON1.23 D6.4 D6.7 U1.24 | length 587.8
  Top w6: U1.24@196.85,-1181.1 196.85,-1190.94 212.03,-1206.12 212.03,-1287.87 255.95,-1331.79 255.95,-1356.84 250.69,-1362.09 D6.7@250.69,-1373.37 D6.4@250.69,-1407.45 250.69,-1418.45 255.95,-1423.71 255.95,-1430.91 v1(246.53,-1440.33) ; CON1.23@254.06,-1685 254.06,-1665.02 277.54,-1641.54 v1(294.41,-1641.54)
  Bottom w6: v1(246.53,-1440.33) 255.98,-1449.77 255.98,-1518.98 279.54,-1542.54 279.54,-1631.16 292.16,-1643.78 292.33,-1643.95 v1(294.41,-1641.54)
MCSIC-CKP: CON1.24 D6.5 D6.6 U1.25 | length 577.5
  Top w6: U1.25@236.22,-1181.1 236.22,-1190.94 222.04,-1205.13 222.04,-1283.65 266.03,-1327.65 266.03,-1358.57 270.37,-1362.91 D6.6@270.37,-1373.37 D6.5@270.37,-1407.45 270.37,-1418.65 266.03,-1422.99 266.03,-1431.83 v1(274.53,-1440.33) ; CON1.24@265.87,-1559.02 265.87,-1603.96 275.94,-1614.04 v1(299.67,-1614.04)
  Bottom w6: v1(274.53,-1440.33) 266.03,-1448.83 266.03,-1514.81 289.54,-1538.32 289.54,-1604.02 v1@304.51,-1618.99 ; v1(299.67,-1614.04) v1@304.27,-1610.2
MCSIC-D0N: CON1.20 D6.1 D6.10 U1.22 | length 567.6
  Top w6: U1.22@118.11,-1181.1 118.11,-1190.94 133.25,-1206.08 133.25,-1273.56 196.55,-1336.86 196.55,-1357.41 191.63,-1362.32 D6.10@191.63,-1373.37 D6.1@191.63,-1407.45 191.63,-1416.56 196.96,-1421.89 196.96,-1431.01 v1(187.48,-1440.49) ; CON1.20@218.63,-1559.02 218.63,-1577.65 247.17,-1606.19 v1(247.17,-1611.07)
  Bottom w6: v1(187.48,-1440.49) 196.91,-1449.93 196.91,-1500.25 257.26,-1560.6 257.26,-1600.98 v1(247.17,-1611.07)
MCSIC-D0P: CON1.21 D6.2 D6.9 U1.23 | length 587
  Top w6: U1.23@157.48,-1181.1 157.48,-1190.94 143.3,-1205.13 143.3,-1269.38 206.98,-1333.07 206.98,-1357.11 211.32,-1361.45 D6.9@211.32,-1373.37 D6.2@211.32,-1407.45 211.32,-1417.75 206.98,-1422.1 206.98,-1431.99 v1(215.48,-1440.49) ; CON1.21@230.44,-1685 230.44,-1667.29 236.25,-1661.48 236.25,-1651.75 v1(248.35,-1639.65)
  Bottom w6: v1(215.48,-1440.49) 206.98,-1448.99 206.98,-1496.18 267.26,-1556.46 267.26,-1620.74 v1(248.35,-1639.65)
MCSIC-D1N: CON1.17 D5.4 D5.7 U1.20 | length 624.2
  Top w6: U1.20@39.37,-1181.1 39.37,-1190.94 53.56,-1205.13 53.56,-1237.52 140.06,-1324.02 140.06,-1357.95 134.87,-1363.14 D5.4@134.87,-1408.34 134.87,-1418.72 140.16,-1424.01 140.16,-1431.47 v1(130.71,-1440.92) ; CON1.17@183.2,-1685 183.2,-1648.48 192.62,-1639.06 218.62,-1639.06 v1(220.26,-1639.72)
  Bottom w6: v1(130.71,-1440.92) 140.21,-1450.41 140.21,-1495.13 198.93,-1553.85 198.93,-1620.58 215.99,-1637.63 218.62,-1639.06 v1(220.26,-1639.72)
MCSIC-D1P: CON1.18 D5.5 D5.6 U1.21 | length 571.8
  Top w6: U1.21@78.74,-1181.1 78.74,-1190.94 63.63,-1206.06 63.63,-1233.44 150.21,-1320.03 150.21,-1358.78 154.55,-1363.12 D5.5@154.55,-1408.34 154.55,-1419.73 150.21,-1424.07 150.21,-1432.42 v1(158.71,-1440.92) ; CON1.18@195.01,-1559.02 195.01,-1586.13 218.96,-1610.08 v1(218.96,-1610.39)
  Bottom w6: v1(158.71,-1440.92) 150.21,-1449.42 150.21,-1490.93 208.94,-1549.66 208.94,-1600.37 v1(218.96,-1610.39)
MDI0+: J18.2 U10.1 | length 662.7
  Top w6: U10.1@1476.38,1265.75 1476.38,1279.69 1473.5,1282.56 1473.5,1311.57 1546,1384.07 1546,1418.75 1591.78,1464.53 1653.43,1464.53 1783.45,1594.55 1783.45,1668.16 1751.73,1699.88 1751.73,1709.21 J18.2@1780.32,1737.8
MDI0-: J18.3 U10.2 | length 665.8
  Top w6: U10.2@1460.63,1265.75 1460.63,1279.77 1463.5,1282.64 1463.5,1315.72 1536,1388.21 1536,1423.16 1587.37,1474.53 1649.14,1474.53 1773.45,1598.84 1773.45,1664.02 1747.02,1690.45 1738.57,1690.45 1730.71,1682.59 J18.3@1730.71,1637.8
MDI1+: J18.4 U10.4 | length 640.1
  Top w6: U10.4@1429.13,1265.75 1429.13,1279.71 1426.26,1282.58 1426.26,1401.03 1586.39,1561.16 1644.32,1561.16 1689.09,1605.93 1689.09,1669.87 1655.61,1703.35 1655.61,1713.09 J18.4@1680.32,1737.8
MDI1-: J18.7 U10.5 | length 918.1
  Top w6: U10.5@1413.39,1265.75 1413.39,1279.69 1416.26,1282.56 1416.26,1405.17 1582.25,1571.16 1640.18,1571.16 1679.09,1610.07 1679.09,1665.73 1640.39,1704.43 1640.39,1753.16 1599.57,1793.98 1551.37,1793.98 1530.71,1773.32 J18.7@1530.71,1637.8
MDI2+: J18.5 U10.6 | length 581.9
  Top w6: U10.6@1397.64,1265.75 1397.64,1279.73 1394.76,1282.6 1394.76,1419.29 1586.58,1611.11 1586.58,1672.88 1593.72,1680.02 1626.11,1680.02 1635.92,1670.21 1635.92,1660.46 1636.09,1637.84 J18.5@1630.71,1637.8
MDI2-: J18.6 U10.7 | length 598.7
  Top w6: U10.7@1381.89,1265.75 1381.89,1279.7 1384.76,1282.57 1384.76,1423.43 1576.58,1615.25 1576.58,1677.02 1589.58,1690.02 1607.29,1690.02 1613.61,1696.34 1613.61,1715.64 1591.45,1737.8 J18.6@1580.32,1737.8
MDI3+: J18.8 U10.9 | length 611.2
  Top w6: U10.9@1350.39,1265.75 1350.39,1281.12 1348.16,1283.35 1348.16,1304.36 1306.54,1345.98 1306.54,1438.13 1485.83,1617.42 1485.83,1674.71 1464.47,1696.07 1449.79,1696.07 1444.22,1701.64 1444.22,1711.9 1470.12,1737.8 J18.8@1480.32,1737.8
MDI3-: J18.9 U10.10 | length 592.7
  Top w6: U10.10@1334.65,1265.75 1334.65,1281.07 1337.9,1284.32 1337.9,1300.48 1296.54,1341.84 1296.54,1442.27 1475.83,1621.56 1475.83,1670.57 1460.33,1686.07 1438.78,1686.07 1430.71,1678 J18.9@1430.71,1637.8
MIC2N: DA1.2 MIC1.2 RA6.1 | length 377.2
  Top w6: MIC1.2@-578.74,2129.92 -544.37,2164.29 -342.42,2164.29 -302.24,2124.12 -302.24,2108.19 RA6.1@-314.96,2095.47 -316.23,2096.74 DA1.2@-350.39,2096.74
MIC2N/MIC3N: CA9.1 UA1.39 | length 321.8
  Top w6: CA9.1@-314.96,1947.83 -301.49,1934.37 -301.49,1920.42 -256.9,1875.83 -256.9,1700.68 -279.28,1678.3 -290.16,1676.21 UA1.39@-298.04,1676.21
MIC2P: DA2.2 MIC1.1 RA5.1 | length 393.8
  Top w6: MIC1.1@-578.74,2208.66 -544.37,2174.29 -338.28,2174.29 -292.24,2128.26 -292.24,2108.19 RA5.1@-279.53,2095.47 -245.36,2095.47 DA2.2@-244.09,2096.74
MIC2P/MIC3P: CA6.1 UA1.37 | length 383.7
  Top w6: UA1.37@-298.04,1644.71 -252.2,1644.71 -235.91,1661.01 -235.91,1688.2 -246.6,1698.89 -246.6,1880.14 -291.49,1925.03 -291.49,1935.87 CA6.1@-279.53,1947.83
MICIN1N: RA25.2 UA1.1 | length 364
  Top w6: RA25.2@-463.58,1944.88 -451.62,1956.85 -437.45,1956.85 -431.55,1950.95 -431.55,1925.47 -412.66,1906.57 -362.67,1906.57 -308.97,1852.87 -308.97,1727.62 -315.11,1721.48 UA1.1@-327.56,1721.48
MICIN1P: RA21.2 UA1.40 | length 399.3
  Top w6: RA21.2@-463.58,1984.25 -451.62,1972.29 -451.62,1971.53 -446.94,1966.85 -433.31,1966.85 -421.55,1955.1 -421.55,1929.61 -408.51,1916.57 -356.46,1916.57 -298.97,1859.08 -298.97,1699.83 -298.04,1698.89 UA1.40@-298.04,1691.95
MICIN4N: C56.1 UA1.4 | length 1642.4
  Top w6: C56.1@-1712.6,1538.39 -1699.2,1538.39 -1696.44,1535.63 -1696.44,1518.69 -1683.85,1506.1 -1630.43,1506.1 -1613.16,1523.37 -1435.36,1523.37 -1426.29,1514.29 v1(-1425.96,1514.62) ; UA1.4@-374.81,1721.48 -374.81,1733.99 -372.43,1736.36 -372.43,1760.57 v1(-368.43,1764.58)
  Bottom w6: v1(-1425.96,1514.62) -1417.77,1522.81 -1050.81,1522.81 -1003.1,1475.1 -576.86,1475.1 -450.8,1601.15 -450.8,1717.89 -396.01,1772.68 -376.53,1772.68 v1(-368.43,1764.58)
MICIN4P: C55.1 UA1.3 | length 1685.3
  Top w6: C55.1@-1669.29,1538.39 -1682.6,1538.39 -1685.44,1535.54 -1685.44,1523.37 -1679.17,1517.1 -1635.02,1517.1 -1617.75,1534.37 -1436.41,1534.37 v1(-1428.2,1542.58) ; v1(-368.59,1792.95) -367.05,1792.6 -365.56,1792.81 -365.61,1793.18 -348.39,1775.96 -348.39,1756.28 -361.43,1743.24 -361.43,1737.23 -359.06,1734.86 UA1.3@-359.06,1721.48
  Bottom w6: v1(-1428.2,1542.58) -1428.2,1542.71 -1426.38,1542.67 -1418.39,1534.68 -1046.52,1534.68 -998.14,1486.3 -581.25,1486.3 -461.82,1605.72 -461.82,1722.5 -400.59,1783.73 -374.31,1783.73 -364.7,1793.33 -366.45,1795.09 -368.87,1797.5 -367,1795.31 -367.54,1794.85 -367.05,1794.26 -366.22,1793.3 -367.05,1792.6 v1(-368.59,1792.95)
N39839: J7.9 R51.2 R53.2 | length 128.6
  Top w6: J7.9@1108.27,1761.81 1108.27,1695.06 R53.2@1124.13,1679.2 R51.2@1163.5,1679.2
N638326: J18.14 R85.1 | length 907.3
  Top w6: R85.1@1197.83,1476.38 1221.31,1476.38 1240.16,1495.22 1240.16,1700.79 1503.94,1964.57 1503.94,2029.92 J18.14@1353.15,2180.71
N638520: J18.11 R82.1 | length 1384.3
  Top w6: R82.1@1709.65,1078.74 1815.25,1078.74 1862.2,1125.7 1862.2,1311.02 1888.23,1337.05 1888.23,1745.63 1704.72,1929.13 1704.72,2010.63 J18.11@1874.8,2180.71
N5679088: C1.2 L1.1 U2.6
N5679096: C1.1 U2.1 | length 86.3
  Top w11.81: U2.1@-2465.16,-819.28 -2465.16,-852.74 -2456.3,-861.6 C1.1@-2415.94,-861.6
N5679154: C4.2 R4.2 R7.1 U2.3 | length 155
  Top w6: U2.3@-2539.96,-819.28 -2539.96,-809.44 -2545.87,-803.53 R7.1@-2545.87,-741.52 R4.2@-2510.43,-741.52 C4.2@-2471.06,-741.52
N16925291: D32.1 L5.2 U7.1 | length 140.4
  Top w6: L5.2@2236.22,2011.81 2220.47,2011.81 2228.23,2019.68 2263.78,2055.75 D32.1@2326.77,2055.75
N17131711: D70.2 R88.1 | length 290.5
  Top w6: R88.1@1874.02,-867.13 1961.61,-867.13 1972.44,-877.95 1972.44,-895.57 D70.2@2092.62,-1015.75
N17175777: Q1.3 R71.2 R72.1 U9.2 U9.3 | length 474.8
  Top w20: Q1.3@1129.92,-1029.87 1259.53,-1029.87 ; U9.3@1270.28,-957.87 1270.28,-1017.87 ; R72.1@1358.27,-882.87 R71.2@1318.9,-882.87 1318.9,-957.87 U9.2@1320.28,-957.87 1320.28,-1015.74 1306.15,-1029.87 1282.28,-1029.87 ; 1259.53,-1029.87 1270.28,-1019.12 ; 1259.53,-1029.87 1268.22,-1029.87 ; 1268.22,-1029.87 1270.28,-1027.81 1270.28,-1019.12 ; 1268.22,-1029.87 1282.28,-1029.87 ; 1270.28,-1019.12 1270.28,-1017.87 ; 1270.28,-1017.87 1282.28,-1029.87
N17175783: D51.2 U9.1 | length 508.3
  Top w6: D51.2@1027.56,-1110.87 1027.56,-1140.82 1032.41,-1145.67 1114.17,-1145.67 1129.92,-1129.92 1129.92,-1090.55 1149.61,-1070.87 1206.96,-1070.87 1228.35,-1049.48 1334.65,-1049.48 1370.28,-1013.85 U9.1@1370.28,-957.87
N17177143: C8.2 L2.1 U3.6
N17177153: C11.2 R9.2 R11.1 U3.3 | length 181
  Top w6: U3.3@-2169.29,108.27 -2088.58,108.27 -2086.61,106.3 C11.2@-2091.54,106.3 R9.2@-2091.54,66.93 -2074.8,50.2 -2074.8,44.29 R11.1@-2058.07,27.56
N17255318: Q2.1 R81.2 | length 132.2
  Top w6: R81.2@-1325.79,-791.34 -1325.79,-809.09 -1326.58,-809.88 -1326.77,-809.69 -1326.77,-884.33 Q2.1@-1299.58,-911.52
N17255336: D56.1 J17.2 Q2.3 | length 437
  Top w19.68: J17.2@-1593.31,-779.53 -1593.31,-847.19 -1566.48,-874.02 Q2.3@-1379.58,-874.02
  Top w23.62: Q2.3@-1379.58,-874.02 -1379.58,-908.56 -1306.46,-981.69 D56.1@-1306.46,-988.19
N17819196: CA18.1 UA1.16 UA1.20 | length 218.9
  Top w6: CA18.1@-590.16,1507.87 -566.16,1507.87 -523.81,1550.22 UA1.20@-498.82,1550.22 -477.65,1550.22 -472.13,1555.74 -472.13,1607.86 -477.49,1613.21 UA1.16@-498.82,1613.21
N17819206: CA19.1 UA1.23 | length 92.4
  Top w6: CA19.1@-480.31,1445.87 -437.8,1488.38 UA1.23@-437.8,1520.69
N17819214: CA19.2 UA1.21 | length 142.4
  Top w6: v1(-499.13,1470.64) -500.27,1470.64 -500.27,1432.36 CA19.2@-480.31,1412.4 ; v1(-486.83,1514.82) -469.3,1514.85 UA1.21@-469.3,1520.69
  Bottom w6: v1(-499.13,1470.64) -499.71,1471.22 -489.59,1481.34 -489.59,1514.82 v1(-486.83,1514.82)
N17819230: CA17.1 UA1.34 | length 105.9
  Top w6: UA1.34@-298.04,1597.47 -261.31,1597.47 -222.9,1559.06 -213.58,1559.06 CA17.1@-209.65,1555.12
N17819689: CA5.2 CA6.2 CA7.1 RA3.2 RA5.2 | length 184
  Top w6: RA5.2@-279.53,2062.01 -285.26,2062.01 -285.26,2020.67 -279.53,2020.67 CA7.1@-278.54,2019.68 ; CA5.2@-240.16,1981.3 CA6.2@-279.53,1981.3 -284.69,1981.3 -284.69,2018.7 -279.53,2018.7 CA7.1@-278.54,2019.68 ; RA3.2@-237.2,2019.68 CA7.1@-278.54,2019.68
N17819691: CA7.2 CA9.2 CA12.1 RA6.2 RA10.2 | length 203.8
  Top w6: CA12.1@-357.28,2019.68 CA7.2@-312.01,2019.68 CA7.2@-307.88,2019.68 ; RA6.2@-314.96,2062.01 -312.01,2059.06 -307.88,2059.06 CA7.2@-307.88,2019.68 ; CA9.2@-313.53,1984.25 -310.58,1981.3 CA9.2@-314.96,1981.3 -314.96,1976.79 -312.71,1979.04 -312.01,1979.74 -307.07,1979.74 -307.07,2019.68 CA7.2@-307.88,2019.68
  Top w9.84: RA10.2@-357.28,1984.25 CA9.2@-313.53,1984.25
N17819723: CA8.2 RA10.1 RA12.1 | length 1136.1
  Top w9.84: RA12.1@-390.75,1944.88 RA10.1@-390.75,1984.25 -404.95,1984.25 -420.38,1999.69 -420.38,2051.54 -441.85,2073 -625.94,2073 -661.44,2108.5 -661.44,2227.95 -625.23,2264.16 -230.52,2264.16 -161.04,2194.68 -161.04,2142.5 CA8.2@-181.1,2122.44
N17819725: CA8.1 RA1.1 RA3.1 | length 95.8
  Top w9.84: RA1.1@-200.79,1981.3 -203.74,1984.25 RA3.1@-203.74,2019.68 -181.1,2042.32 CA8.1@-181.1,2066.54
N17838408: C55.2 R66.1 | length 45.3
  Top w6: C55.2@-1669.29,1571.85 R66.1@-1669.29,1617.13
N17838410: C56.2 R68.1 | length 45.3
  Top w6: C56.2@-1712.6,1571.85 R68.1@-1712.6,1617.13
N17838457: C52.1 D48.2 J11.3 R63.2 R67.1 | length 560.4
  Top w6: R67.1@-1625.98,1782.48 -1625.98,1782.78 -1604.39,1782.78 ; R63.2@-1582.68,1782.48 -1582.68,1782.78 -1604.39,1782.78 ; C52.1@-1409.45,1737.2 -1428.45,1756.2 -1428.45,1798.21 D48.2@-1409.45,1817.21 D48.2@-1409.45,1819.21 ; J11.3@-1381.89,1948.82 -1409.45,1948.82 D48.2@-1409.45,1819.21 ; -1604.39,1782.78 -1604.39,1826.65 -1580.64,1850.39 -1440.63,1850.39 D48.2@-1409.45,1819.21
N17838500: C53.1 D50.2 J11.4 | length 454.3
  Top w6: J11.4@-1381.89,2117.72 -1359.61,2117.72 -1313.83,2071.94 -1313.83,1894.83 -1354.33,1854.33 D50.2@-1354.33,1817.21 -1354.33,1815.94 -1373.33,1796.94 -1373.33,1756.21 C53.1@-1354.33,1737.2
N17838683: D49.2 R61.2 R62.2 R63.1 | length 132.5
  Top w6: R63.1@-1582.68,1815.94 -1539.37,1815.94 D49.2@-1539.37,1817.21 -1496.06,1817.21 R61.2@-1496.06,1815.94 R62.2@-1452.76,1815.94
N17845378: C48.2 R56.2 R57.2 | length 88.6
  Top w15: R56.2@-988.19,1579.72 R57.2@-948.82,1579.72 C48.2@-948.82,1628.94
N17845396: C50.2 R59.2 R60.2 | length 88.6
  Top w15: C50.2@-901.57,1628.94 R60.2@-901.57,1579.72 R59.2@-862.2,1579.72
N17845478: C48.1 U8.3 | length 72
  Top w15: U8.3@-951.07,1732.16 -951.07,1662.4 C48.1@-948.82,1662.4
N17845505: C50.1 R58.1 U8.4 | length 190.4
  Top w15: C50.1@-901.57,1662.4 -901.07,1662.4 U8.4@-901.07,1732.16 -901.07,1775.11 R58.1@-846.46,1829.72
N17845570: C47.1 U8.2 | length 70.8
  Top w15: U8.2@-1001.07,1732.16 -1001.07,1662.4 C47.1@-1000,1662.4
N17874598: CA20.2 CA21.1 CA23.1 RA27.1 RA28.2 | length 179.4
  Top w6: RA28.2@-727.36,1980.31 -688.98,1980.31 CA23.1@-688.98,1981.3 RA27.1@-653.54,1981.3 ; RA27.1@-653.54,1987.2 RA27.1@-653.54,1981.3 ; CA21.1@-571.85,1984.25 -571.85,1980.31 -611.22,1980.31 -611.22,1984.25 CA20.2@-614.17,1987.2 -614.17,1980.31 -653.54,1980.31 RA27.1@-653.54,1981.3
N17874616: CA23.2 CA24.1 CA26.1 RA29.2 RA30.2 | length 199.4
  Top w6: RA29.2@-727.36,1944.88 -723.43,1948.82 CA23.2@-688.58,1948.82 ; RA30.2@-653.54,1945.87 RA30.2@-653.54,1952.76 ; CA26.1@-614.17,1945.87 CA26.1@-614.17,1952.76 ; CA24.1@-571.85,1944.88 -566.93,1944.88 -567.91,1945.87 -567.91,1952.76 CA26.1@-614.17,1952.76 ; CA23.2@-688.58,1948.82 -685.04,1948.82 CA23.2@-688.98,1947.83 CA23.2@-688.58,1948.82 ; CA23.2@-688.58,1948.82 -687.01,1952.76 RA30.2@-653.54,1952.76 ; RA30.2@-653.54,1952.76 CA26.1@-614.17,1952.76
N17874634: CA22.2 RA28.1 | length 41.3
  Top w6: CA22.2@-802.17,1980.31 RA28.1@-760.83,1980.31
N17874636: CA25.2 RA29.1 | length 41.3
  Top w6: CA25.2@-802.17,1944.88 RA29.1@-760.83,1944.88
N17914651: C29.2 C36.1 D31.1 L4.2 U6.1 | length 170.5
  Top w6: L4.2@2236.22,1692.91 2267.72,1661.42 2305.67,1661.42 2304.69,1662.4 D31.1@2323.19,1649.61 2330.71,1624.61 C29.2@2330.71,1586.61
N17914681: C29.1 D26.3
N17914691: C37.2 D29.1 R33.1
N17914697: R39.1 R42.1 U6.3 | length 118.9
  Top w6: U6.3@2232.28,1891.73 2271.16,1891.73 2284.94,1905.51 R42.1@2310.04,1905.51 R39.1@2310.04,1870.08
N17914762: C30.1 D26.2 R29.1
N17915278: J4.6 R17.2 R18.1 | length 240.8
  Top w6: R18.1@2292.32,1031.5 R17.2@2333.66,1031.5 2352.5,1012.65 2384.52,1012.65 2385.5,1013.64 2433.65,1013.64 2474.84,972.44 J4.6@2507.87,972.44
N17963617: RU2.2 U13.3 | length 49.6
  Top w6: RU2.2@-2063.98,1385.83 -2063.98,1434.06 U13.3@-2062.99,1435.04
N17967469: U11.12 X2.1 | length 244.4
  Top w8: U11.12@208.66,1773.03 224.41,1773.03 239.08,1787.7 239.08,1920.8 271.65,1953.37 271.65,1958.66 285.43,1972.44 X2.1@285.43,1976.38
N17967471: U11.11 X2.3 | length 310.9
  Top w8: U11.11@208.66,1752.17 224.41,1752.17 251.81,1779.57 251.81,1913.59 259.48,1921.26 316.93,1921.26 352.36,1885.83 X2.3@352.36,1881.89
N17967477: C64.1 U11.10 | length 163.3
  Top w6: U11.10@208.66,1731.3 232.45,1731.3 271.83,1770.68 271.83,1787.58 303.15,1818.9 C64.1@325.79,1818.9
N18037700: R233.2 U3.4 | length 90.4
  Top w6: R233.2@-2369.09,106.3 -2367.13,108.27 U3.4@-2279.53,108.27
N18103307: CB4.2 J12.49 | length 138.6
  Top w6: CB4.2@-1271.65,1274.61 -1284.37,1261.89 -1284.37,1245.96 -1254.85,1216.44 -1254.85,1187.21 -1250,1182.37 J12.49@-1250,1155.5
N18103321: CB5.2 J12.47 | length 138.6
  Top w6: CB5.2@-1307.09,1274.61 -1294.37,1261.89 -1294.37,1241.82 -1264.85,1212.3 -1264.85,1187.71 -1269.69,1182.86 J12.47@-1269.69,1155.5
N18104730: CON2.17 R21.2 | length 154.3
  Top w6: CON2.17@-2828.74,-257.87 -2750,-257.87 -2712.6,-220.47 R21.2@-2689.96,-220.47
N18104732: CON2.22 R22.2 | length 144.5
  Top w6: CON2.22@-2828.74,-159.45 -2703.74,-159.45 R22.2@-2689.96,-145.67
N18104734: CON2.23 R26.2 | length 152.6
  Top w6: CON2.23@-2828.74,-139.76 -2723.42,-139.76 R26.2@-2689.96,-106.3
N18105041: C21.2 CON2.3 | length 239.9
  Top w6: CON2.3@-2828.74,-533.46 -2809.06,-533.46 -2804.21,-528.62 -2678.43,-528.62 -2657.03,-550.03 -2625.7,-550.03 -2609.5,-566.23 -2607.98,-566.23 C21.2@-2607.98,-564.71
N18105043: C22.2 CON2.4 | length 239.9
  Top w6: CON2.4@-2828.74,-513.78 -2809.06,-513.78 -2804.21,-518.62 -2674.29,-518.62 -2652.89,-540.03 -2625.7,-540.03 -2609.5,-523.82 -2607.98,-523.82 C22.2@-2607.98,-525.34
N18105045: C25.2 CON2.9 | length 236.3
  Top w6: CON2.9@-2828.74,-415.35 -2809.06,-415.35 -2804.21,-410.51 -2662.71,-410.51 -2644.74,-392.54 -2622.66,-392.54 C25.2@-2607.98,-407.23
N18105047: C28.2 CON2.10 | length 236.3
  Top w6: CON2.10@-2828.74,-395.67 -2809.06,-395.67 -2804.21,-400.51 -2666.85,-400.51 -2648.89,-382.55 -2622.66,-382.55 C28.2@-2607.98,-367.86
N18105049: C23.2 CON2.6 | length 229.6
  Top w6: CON2.6@-2828.74,-474.41 -2809.06,-474.41 -2804.21,-469.57 -2624.38,-469.57 C23.2@-2607.98,-485.97
N18105059: C24.2 CON2.7 | length 230.7
  Top w6: CON2.7@-2828.74,-454.72 -2809.06,-454.72 -2804.21,-459.57 -2620.98,-459.57 -2612.31,-450.89 -2607.98,-450.89 C24.2@-2607.98,-446.6
N18142204: CON3.42 R101.1 | length 1025.1
  Top w6: R101.1@-3036.42,1366.14 -3055.12,1366.14 -3066.93,1354.33 -3066.93,1287.4 -3051.18,1271.65 -2980.31,1271.65 -2968.5,1259.84 -2968.5,1086.61 -2901.57,1019.68 -2901.57,976.38 -2964.57,913.39 -2964.57,759.84 -2952.76,748.03 -2775.59,748.03 -2767.72,755.91 CON3.42@-2767.72,810.04
N18142206: D73.2 R101.2 | length 66.3
  Top w6: D73.2@-3030,1311.02 -3002.95,1338.07 R101.2@-3002.95,1366.14
N18142901: U42.12 X3.1 | length 217.6
  Top w6: U42.12@-2405.51,1426.57 -2373.27,1426.57 -2347.09,1452.76 -2250,1452.76 -2216.54,1486.22 X3.1@-2212.6,1486.22
N18142903: U42.11 X3.3 | length 104.1
  Top w6: U42.11@-2405.51,1405.71 -2362.01,1405.71 -2348.43,1419.29 X3.3@-2307.09,1419.29
N18142917: C86.1 U42.10 | length 97.3
  Top w6: U42.10@-2405.51,1384.84 -2373.03,1384.84 -2354.33,1366.14 C86.1@-2315.94,1366.14
N18148334: C89.2 L7.1 U43.6
N18148344: C92.2 R116.1 R117.2 U43.3 | length 149.4
  Top w6: U43.3@-2169.29,466.54 -2159.45,466.54 -2157.48,468.5 R117.2@-2091.54,468.5 C92.2@-2091.54,433.07 R116.1@-2091.54,397.64
N18193662: D84.2 R228.1 R230.1 R232.1 | length 416.9
  Top w6: D84.2@-1582.05,535.43 -1582.05,529.42 -1552.48,499.85 -1447.98,499.85 R232.1@-1429.13,518.7 -1406.44,496 -1353.41,496 R230.1@-1330.71,518.7 -1308.56,496.55 -1250.5,496.55 R228.1@-1228.35,518.7
N18243800: R157.2 R158.1 U44.1 | length 125.1
  Top w6: U44.1@-2285.43,-1157.48 -2289.58,-1157.48 -2287.51,-1155.41 -2285.64,-1153.54 R158.1@-2209.65,-1153.54 R157.2@-2209.65,-1192.91
N18243874: C323.2 R159.2 U44.5 | length 194.2
  Top w6: R159.2@-2330.71,-1390.75 -2310.88,-1390.75 ; U44.5@-2322.83,-1267.72 -2322.83,-1299.03 -2305.71,-1316.16 -2305.71,-1385.91 ; C323.2@-2282.08,-1389.42 -2282.08,-1390.75 -2300.75,-1390.75 ; -2310.88,-1390.75 -2306.04,-1385.91 -2305.71,-1385.91 ; -2310.88,-1390.75 -2305.71,-1390.75 ; -2305.71,-1390.75 -2300.75,-1390.75 ; -2305.71,-1390.75 -2305.71,-1385.91 ; -2305.71,-1385.91 -2305.59,-1385.91 -2300.75,-1390.75
N18245140: J2.3 R238.1 R239.2 | length 735.8
  Top w6: J2.3@-2555.12,-1622.05 -2555.12,-1631.42 -2540.87,-1645.67 -2539.37,-1645.67 -2500,-1685.04 -2401.57,-1685.04 -2370.08,-1653.54 -2370.08,-1586.61 -2338.58,-1555.12 -2307.09,-1555.12 -2209.65,-1457.68 R238.1@-2209.65,-1232.28
N18245142: J2.2 U44.2 | length 644.7
  Top w6: J2.2@-2437.01,-1622.05 -2437.01,-1612.68 -2355.83,-1531.5 -2311.02,-1531.5 -2231.97,-1452.44 -2231.97,-1208.66 -2243.78,-1196.85 -2297.24,-1196.85 -2322.83,-1171.26 U44.2@-2322.83,-1157.48
N18248395: D2.1 R6.2 R240.1 | length 114.3
  Top w6: R240.1@-2176.18,-1114.17 D2.1@-2112.68,-1114.17 -2112.68,-1120.55 -2114.17,-1122.05 R6.2@-2114.17,-1164.37
N18249325: D2.2 R241.2 | length 54.1
  Top w6: D2.2@-2052.68,-1114.17 -2043.31,-1123.54 R241.2@-2043.31,-1164.37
